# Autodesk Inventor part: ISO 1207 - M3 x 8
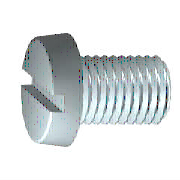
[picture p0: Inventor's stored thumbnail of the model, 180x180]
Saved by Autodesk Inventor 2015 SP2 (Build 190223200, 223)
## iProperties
Created: 2014-02
Part Number: ISO 1207 - M3 x 8
Material: Edelstahl, 440C
Description: Zylinderschraube mit Schlitz
Document SubType Name: Modeling
Standard: ISO 1207
Designer: ryll
Standard Revision: 1994
Standards Organization: DIN
Language: de-DE
Size Designation: M3 x 8
Categories: <MemberInstance><Categories><Category DisplayName="Verbindungselemente" InternalName="e4da775c-781d-43d5-af7c-5136215cf5a6" Mnemonic="FSTN"><Category DisplayNam
Density: 7.75 g/cm^3
Appearance: Halbpoliert
IsCustomPart: 0
Author: ryll
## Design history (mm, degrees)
body "Solid1"
revolve "Körper" stored, may be unused: angle "d8" = 90 deg
sketch "Skizze2"
  geometry: L1 (0, 0)-(0, 2.575) reference; L2 (-2.75, 0.5)-(2.75, 0.5); L3 (2.75, 0.5)-(2.75, -0.5); L4 (2.75, -0.5)-(-2.75, -0.5); L5 (-2.75, -0.5)-(-2.75, 0.5); L6 (-2.75, 0)-(2.75, 0); L7 (0, 0.5)-(0, -0.5); C1 r 2.75 at (0, 0) reference; 1 further point
  constraints: 12 end point, 5 midpoint, 2 parallel, 1 collinear, 1 horizontal, 1 perpendicular
  dimensions: "d11" = 1 distance of L4.end L2.start (= SBR); "d12" = 5.5 distance of L2.start L2.end (= KOD)
fillet "Rundung1" dims "d14" = 0.1 (= RR)
extrude "Loch" cut sketch "Skizze2" distance "d19" = 0.85 (= STI); taper "d20" = 0 deg
feature "Gewinde" dims "d15" = 7 (= GEL), "d16" = 0
chamfer "Fase1" distance "d17" = 0.30673 (= -0.5 x SPD + 0.5 x GD); stored, may be unused: second distance "d18" = 0.30683 (computed from GUL), angle "d36" = 45 deg
workplane "Work Plane1"
sketch "Skizze1"
  geometry: L1 (-2, 0)-(8, 0); L2 (8, 0)-(8, 1.5); L3 (8, 1.5)-(1, 1.5); L4 (1, 1.5)-(0.693, 1.347); L5 (0.693, 1.347)-(0, 1.347); L6 (0, 1.347)-(0, 2.75); L7 (-4, 0)-(10, 0) reference; L8 (0, -0.55)-(0, 3.3) reference; L9 (-2, 0)-(-2, 2.575); L10 (0, 2.75)-(-2, 2.575); L11 (1, 1.5)-(0, 1.5)
  constraints: 18 end point, 4 parallel, 2 collinear, 2 perpendicular, 1 horizontal, 1 point on line
  dimensions: "d0" = 8 distance between parallel lines of L2 L6 (= NLG); "d1" = 7 distance from line of L3.end L2 (= GEL); "d2" = 0.30683 horizontal distance of L4.end L3.end (computed from GAL); "d3" = 2 distance from line of L1.start L6 (= KOH); "d4" = 3 diameter of L3 L1 (= GD); "d5" = 2.6935 diameter of L5 L1 (= BDM); "d9" = 5.5 diameter of L6.end L1 (= KOD); "d10" = 5 deg angle of L10 L1 (= KEWI)
other parameters: "GD" = 3 (= NND) [user parameter; used in 2 equation terms], "NLG" = 8 [user parameter; used in 1 equation term], "GEL" = 7 [user parameter; used in 2 equation terms], "KOD" = 5.5 [user parameter; used in 2 equation terms], "KOH" = 2 [user parameter; used in 1 equation term], "GAL" = 0.30673 (= 0.61345 x PTC) [user parameter; used in 1 equation term], "SPD" = 2.38655 (= NND - 1.2269 x PTC) [user parameter; used in 1 equation term], "BDM" = 2.6935 [user parameter; used in 1 equation term], "GUL" = 0.30673 (= 0.61345 x PTC) [user parameter; used in 1 equation term], "RR" = 0.1 [user parameter; used in 1 equation term], "d7" = 0, "SBR" = 1 [user parameter; used in 1 equation term], "STI" = 0.85 [user parameter; used in 1 equation term], "KEWI" = 5 deg [user parameter; used in 1 equation term], "d37" = 0, "d39" = 0, "PTC" = 0.5 [user parameter; used in 5 equation terms], "THREADDIA" = 3 [user parameter; used in 1 equation term], "TOA" = 30 deg [user parameter], "NND" = 3 [user parameter; used in 2 equation terms], "GD1" = 2.38655 (= THREADDIA - 1.2269 x PTC) [user parameter]
